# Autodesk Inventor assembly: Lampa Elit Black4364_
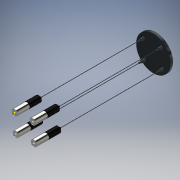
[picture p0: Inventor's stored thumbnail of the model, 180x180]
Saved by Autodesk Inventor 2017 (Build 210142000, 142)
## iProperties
Created: 2020-09
Part Number: Lampa Elit Black4364_
Document SubType Name: Assembly
Designer: Admin
Author: Admin
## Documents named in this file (3)
- D:\TK Lighting\Elit Black\Lampa Elit Black4364_.iam
- D:\TK Lighting\Logan Black\Lampa Logan Black_285.iam
- D:\TK Lighting\Logan Black\Elit 285 zawiesie kolo.ipt
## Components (5 placed, 2 different names)
1. Lampa Logan Black_285:1 [sub-assembly] — Mate:4, Mate:8
2. Lampa Logan Black_285:2 [sub-assembly] — Mate:1, Mate:5
3. Lampa Logan Black_285:3 [sub-assembly] — Mate:2, Mate:6
4. Lampa Logan Black_285:4 [sub-assembly] — Mate:3, Mate:7
5. Elit 285 zawiesie kolo:1 — Mate:1, Mate:2, Mate:3, Mate:4, Mate:5, Mate:6, Mate:7, Mate:8
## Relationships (8: Mate 8)
- Mate:1: Lampa Logan Black_285:2 ↔ Elit 285 zawiesie kolo:1
- Mate:2: Lampa Logan Black_285:3 ↔ Elit 285 zawiesie kolo:1
- Mate:3: Lampa Logan Black_285:4 ↔ Elit 285 zawiesie kolo:1
- Mate:4: Lampa Logan Black_285:1 ↔ Elit 285 zawiesie kolo:1
- Mate:5: Lampa Logan Black_285:2 ↔ Elit 285 zawiesie kolo:1
- Mate:6: Lampa Logan Black_285:3 ↔ Elit 285 zawiesie kolo:1
- Mate:7: Lampa Logan Black_285:4 ↔ Elit 285 zawiesie kolo:1
- Mate:8: Lampa Logan Black_285:1 ↔ Elit 285 zawiesie kolo:1
